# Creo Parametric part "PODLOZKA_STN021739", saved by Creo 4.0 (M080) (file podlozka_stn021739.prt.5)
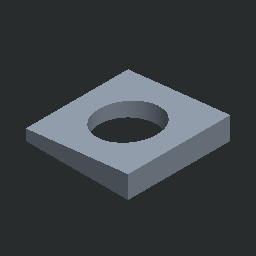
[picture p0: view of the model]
Units: millimeter Kilogram Sec (mmKs); MM, KILOGRAM, SECS
Materials in the file: OCEL_N

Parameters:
  MFG_WP_MATERIAL = "OCEL"
  NAZOV = "PODLOZKA_STN021739"
  NORMA = "STN 02 1739"
  PTC_MATERIAL_NAME = "OCEL_N"

Other parameters: HMOTNOST, HUSTOTA, D1, D5, D6

Created from: C021739.PRT

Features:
  1. hole

Layers: 1, 2, 3, 4, 5, 6, 7, 8, 9, 10, 11, 12, 13, 14, 15, 16, 17, 18, 19, 20, 21, 22, 23, 24, 25, 26, 27, 28, 29, 30, 31, 32

Family table entries: GENERIC, PODLOZKA_9, PODLOZKA_STN021739, value(d_val), 2/0, value(i_val), PODLOZKA_11, PODLOZKA_STN021739, !/&, 2/4, PODLOZKA_14, PODLOZKA_STN021739, !/,, 2/:, PODLOZKA_18, PODLOZKA_STN021739, !/2, 2/@, PODLOZKA_22, PODLOZKA_STN021739, !/6, 2/D, 2/ , PODLOZKA_26, PODLOZKA_STN021739, !/:, 2/H, 2/", # Pro/TABLE, [] S 92;, [] W 10;, [A] W  3;, [B] W 12;, [C] W 10;, [D] W 10;, [E] W 10;, [F] W 10;

Surfaces: 6 plane, 1 cylinder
